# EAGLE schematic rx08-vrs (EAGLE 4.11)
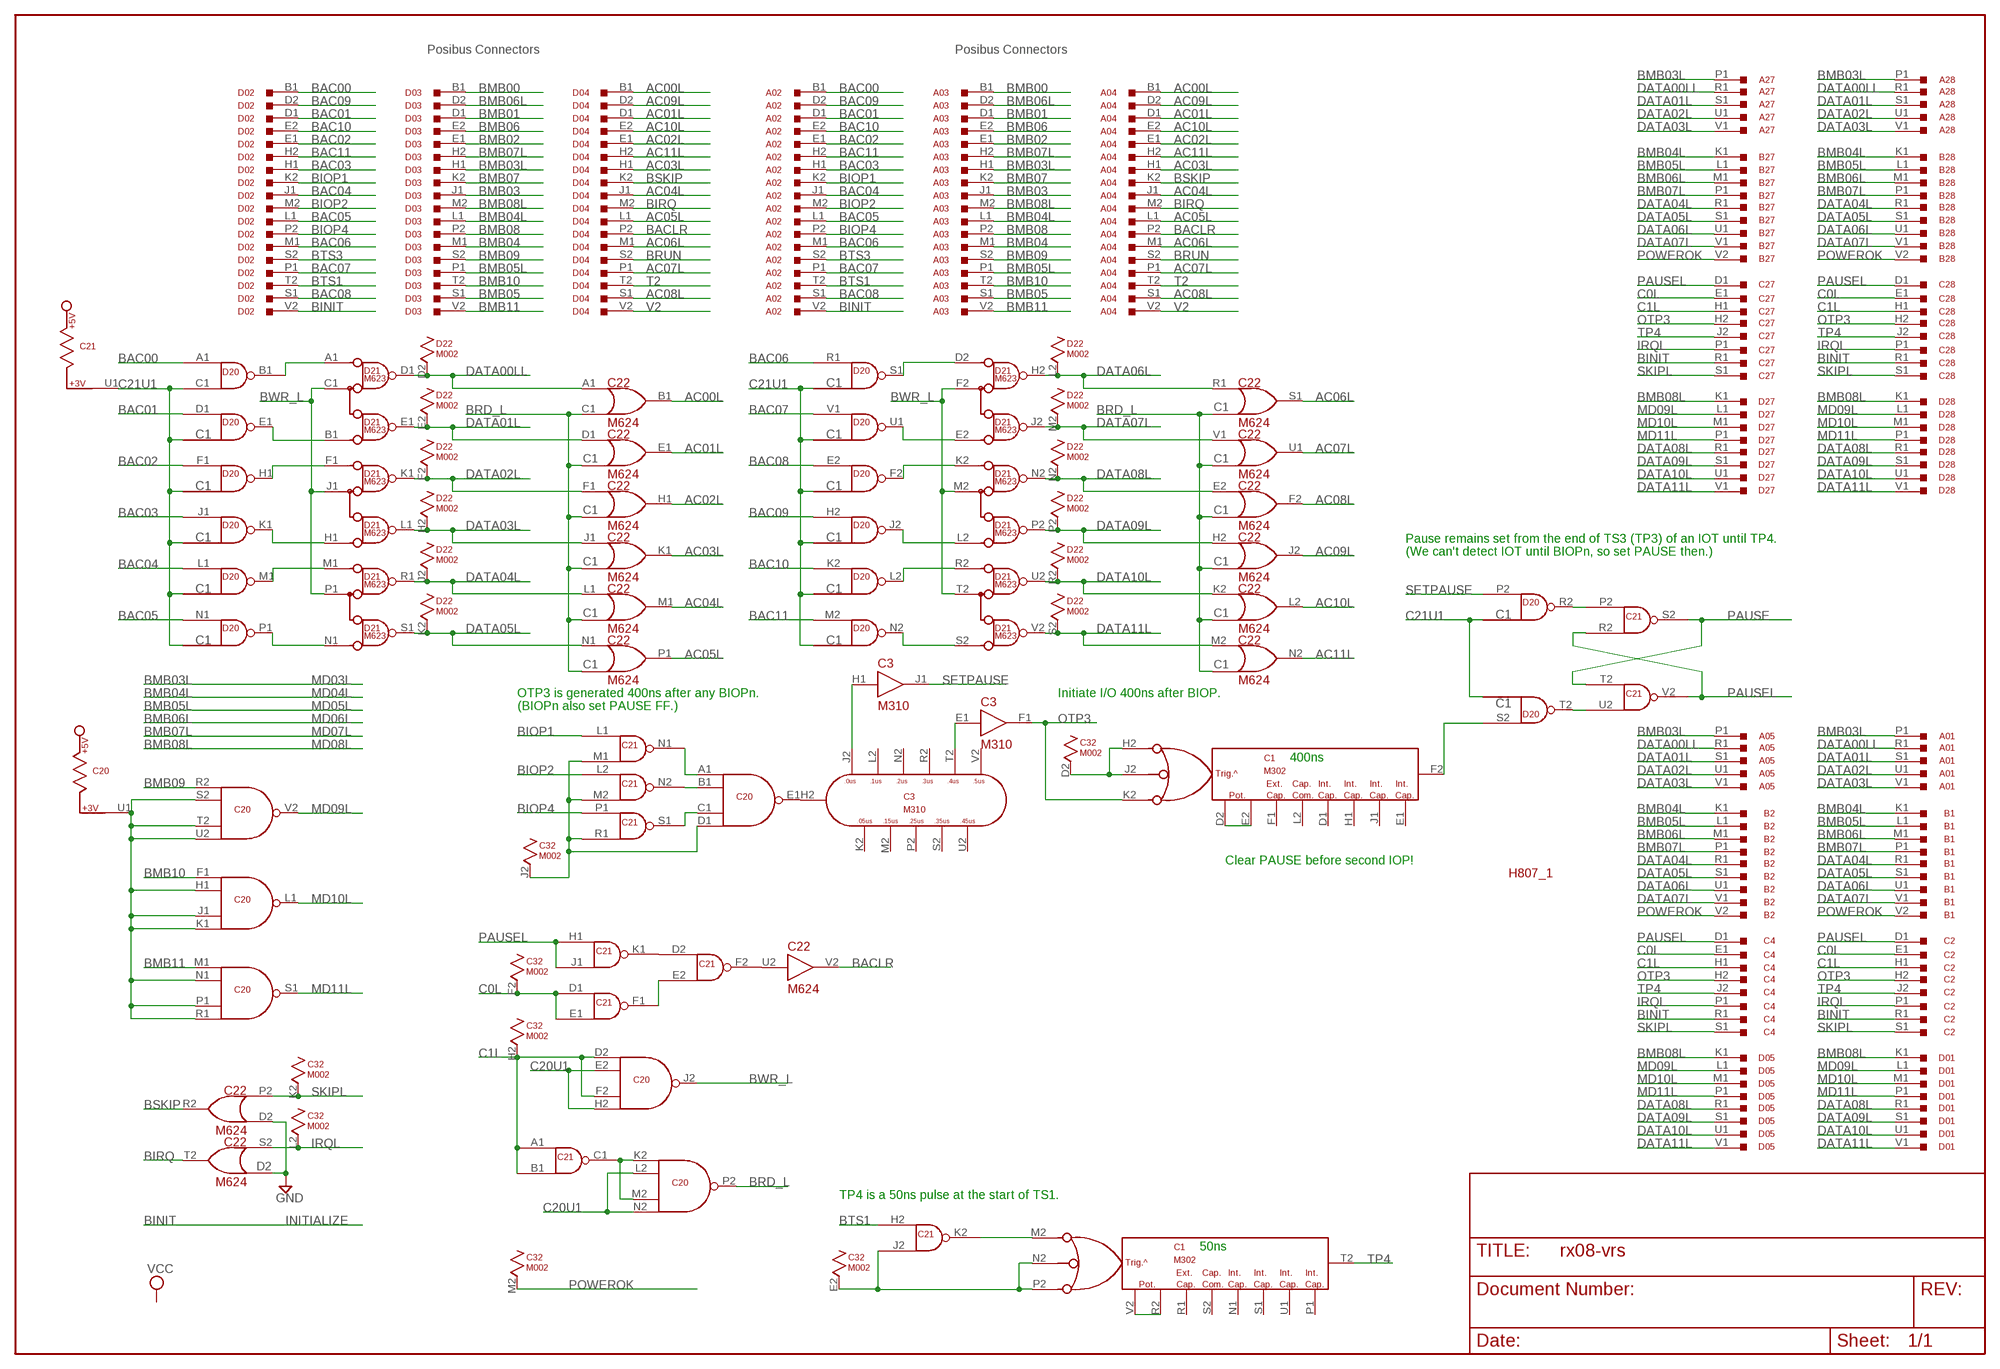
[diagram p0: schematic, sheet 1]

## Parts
A01  M916  [H807]
A02  M903  [H807]
A03  M903  [H807]
A04  M903  [H807]
A05  M916  [H807]
A27  M916  [H807]
A28  M916  [H807]
B1  M916  [H807]
B2  M916  [H807]
B27  M916  [H807]
B28  M916  [H807]
C1  M302  [H807]
C2  M916  [H807]
C3  M310  [H807]
C4  M916  [H807]
C20  M617  [H807]
C21  M113  [H807]
C22  M624  [H807]
C27  M916  [H807]
C28  M916  [H807]
C32  M002  [H807]
D01  M916  [H807]
D02  M903  [H807]
D03  M903  [H807]
D04  M903  [H807]
D05  M916  [H807]
D20  M101  [H807]
D21  M623  [H807]
D22  M002  [H807]
D27  M916  [H807]
D28  M916  [H807]
H807_1  H807  [H807]

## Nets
AC00L: A04.B1 C22.B1(OUT) D04.B1
AC01L: A04.D1 C22.E1(OUT) D04.D1
AC02L: A04.E1 C22.H1(OUT) D04.E1
AC03L: A04.H1 C22.K1(OUT) D04.H1
AC04L: A04.J1 C22.M1(OUT) D04.J1
AC05L: A04.L1 C22.P1(OUT) D04.L1
AC06L: A04.M1 C22.S1(OUT) D04.M1
AC07L: A04.P1 C22.U1(OUT) D04.P1
AC08L: A04.S1 C22.F2(OUT) D04.S1
AC09L: A04.D2 C22.J2(OUT) D04.D2
AC10L: A04.E2 C22.L2(OUT) D04.E2
AC11L: A04.H2 C22.N2(OUT) D04.H2
BAC00: A02.B1 D02.B1 D20.A1(IN1)
BAC01: A02.D1 D02.D1 D20.D1(IN)
BAC02: A02.E1 D02.E1 D20.F1(IN)
BAC03: A02.H1 D02.H1 D20.J1(IN)
BAC04: A02.J1 D02.J1 D20.L1(IN)
BAC05: A02.L1 D02.L1 D20.N1(IN)
BAC06: A02.M1 D02.M1 D20.R1(IN)
BAC07: A02.P1 D02.P1 D20.V1(IN)
BAC08: A02.S1 D02.S1 D20.E2(IN)
BAC09: A02.D2 D02.D2 D20.H2(IN)
BAC10: A02.E2 D02.E2 D20.K2(IN)
BAC11: A02.H2 D02.H2 D20.M2(IN)
BACLR: A04.P2 C22.V2(OUT) D04.P2
BINIT: A02.V2 C2.R1 C4.R1 C27.R1 C28.R1 D02.V2
BIOP1: A02.K2 C21.L1(IN1) D02.K2
BIOP2: A02.M2 C21.L2(IN1) D02.M2
BIOP4: A02.P2 C21.P1(IN1) D02.P2
BIRQ: A04.M2 C22.T2(OUT) D04.M2
BMB00: A03.B1 D03.B1
BMB01: A03.D1 D03.D1
BMB02: A03.E1 D03.E1
BMB03: A03.J1 D03.J1
BMB03L: A01.P1 A03.H1 A05.P1 A27.P1 A28.P1 D03.H1
BMB04: A03.M1 D03.M1
BMB04L: A03.L1 B1.K1 B2.K1 B27.K1 B28.K1 D03.L1
BMB05: A03.S1 D03.S1
BMB05L: A03.P1 B1.L1 B2.L1 B27.L1 B28.L1 D03.P1
BMB06: A03.E2 D03.E2
BMB06L: A03.D2 B1.M1 B2.M1 B27.M1 B28.M1 D03.D2
BMB07: A03.K2 D03.K2
BMB07L: A03.H2 B1.P1 B2.P1 B27.P1 B28.P1 D03.H2
BMB08: A03.P2 D03.P2
BMB08L: A03.M2 D01.K1 D03.M2 D05.K1 D27.K1 D28.K1
BMB09: A03.S2 C20.R2(IN1) D03.S2
BMB10: A03.T2 C20.F1(IN1) D03.T2
BMB11: A03.V2 C20.M1(IN1) D03.V2
BRD_L: C20.P2(OUT) C22.C1(IN2)
BRUN: A04.S2 D04.S2
BSKIP: A04.K2 C22.R2(OUT) D04.K2
BTS1: A02.T2 C21.H2(IN1) D02.T2
BTS3: A02.S2 D02.S2
BWR_L: C20.J2(OUT) D21.C1(C) D21.F2(C) D21.J1(C) D21.M2(C) D21.P1(C) D21.T2(C)
C0L: C2.E1 C4.E1 C21.D1(IN1) C21.E1(IN2) C27.E1 C28.E1 C32.F2
C1L: C2.H1 C4.H1 C20.D2(IN1) C20.F2(IN3) C21.A1(IN1) C21.B1(IN2) C27.H1 C28.H1 C32.H2
C20U1: C20.E2(IN2) C20.H1(IN2) C20.H2(IN4) C20.J1(IN3) C20.K1(IN4) C20.L2(IN2) C20.N1(IN2) C20.N2(IN4) C20.P1(IN3) C20.R1(IN4) C20.S2(IN2) C20.T2(IN3) C20.U1 C20.U2(IN4)
C21U1: C21.U1 D20.C1(IN2)
DATA00LL: A01.R1 A05.R1 A27.R1 A28.R1 C22.A1(IN1) D21.D1(D) D22.D2
DATA01L: A01.S1 A05.S1 A27.S1 A28.S1 C22.D1(IN) D21.E1(E) D22.E2
DATA02L: A01.U1 A05.U1 A27.U1 A28.U1 C22.F1(IN) D21.K1(D) D22.F2
DATA03L: A01.V1 A05.V1 A27.V1 A28.V1 C22.J1(IN) D21.L1(E) D22.H2
DATA04L: B1.R1 B2.R1 B27.R1 B28.R1 C22.L1(IN) D21.R1(D) D22.J2
DATA05L: B1.S1 B2.S1 B27.S1 B28.S1 C22.N1(IN) D21.S1(E) D22.K2
DATA06L: B1.U1 B2.U1 B27.U1 B28.U1 C22.R1(IN) D21.H2(D) D22.L2
DATA07L: B1.V1 B2.V1 B27.V1 B28.V1 C22.V1(IN) D21.J2(E) D22.M2
DATA08L: C22.E2(IN) D01.R1 D05.R1 D21.N2(D) D22.N2 D27.R1 D28.R1
DATA09L: C22.H2(IN) D01.S1 D05.S1 D21.P2(E) D22.P2 D27.S1 D28.S1
DATA10L: C22.K2(IN) D01.U1 D05.U1 D21.U2(D) D22.R2 D27.U1 D28.U1
DATA11L: C22.M2(IN) D01.V1 D05.V1 D21.V2(E) D22.S2 D27.V1 D28.V1
GND: C22.D2(IN2)
IRQL: C2.P1 C4.P1 C22.S2(IN) C27.P1 C28.P1 C32.L2
MD09L: C20.V2(OUT) D01.L1 D05.L1 D27.L1 D28.L1
MD10L: C20.L1(OUT) D01.M1 D05.M1 D27.M1 D28.M1
MD11L: C20.S1(OUT) D01.P1 D05.P1 D27.P1 D28.P1
N$1: D20.B1(OUT) D21.A1(A)
N$2: D20.E1(OUT) D21.B1(B)
N$3: D20.H1(OUT) D21.F1(A)
N$4: D20.K1(OUT) D21.H1(B)
N$5: D20.P1(OUT) D21.N1(B)
N$6: D20.M1(OUT) D21.M1(A)
N$7: C20.K2(IN1) C20.M2(IN3) C21.C1(OUT)
N$8: D20.N2(OUT) D21.S2(B)
N$9: C1.F2 D20.S2(IN)
N$10: D20.J2(OUT) D21.L2(B)
N$11: D20.U1(OUT) D21.E2(B)
N$12: D20.S1(OUT) D21.D2(A)
N$13: D20.F2(OUT) D21.K2(A)
N$14: D20.L2(OUT) D21.R2(A)
N$15: C21.P2(IN1) D20.R2(OUT)
N$16: C1.H2 C1.J2 C32.D2
N$17: C21.U2(IN2) D20.T2(OUT)
N$19: C21.E2(IN2) C21.F1(OUT)
N$20: C21.D2(IN1) C21.K1(OUT)
N$23: C21.F2(OUT) C22.U2(IN)
N$27: C3.H2 C20.E1(OUT)
N$31: C3.E1(IN) C3.T2
N$32: C20.C1(IN3) C21.S1(OUT)
N$33: C20.A1(IN1) C21.N1(OUT)
N$34: C20.B1(IN2) C21.N2(OUT)
N$35: C1.D2 C1.E2
N$36: C1.M2(H2) C21.K2(OUT)
N$37: C1.R2(E2) C1.V2(D2)
N$38: C3.H1(IN) C3.J2
N$40: C1.N2(J2) C1.P2(K2) C21.J2(IN2) C32.E2
N$43: C20.D1(IN4) C21.M1(IN2) C21.M2(IN2) C21.R1(IN2) C32.J2
OTP3: C1.K2 C2.H2 C3.F1(OUT) C4.H2 C27.H2 C28.H2
PAUSE: C21.S2(OUT) C21.T2(IN1)
PAUSEL: C2.D1 C4.D1 C21.H1(IN1) C21.J1(IN2) C21.R2(IN2) C21.V2(OUT) C27.D1 C28.D1
POWEROK: B1.V2 B2.V2 B27.V2 B28.V2 C32.M2
SETPAUSE: C3.J1(OUT) D20.P2(IN)
SKIPL: C2.S1 C4.S1 C22.P2(IN1) C27.S1 C28.S1 C32.K2
T2: A04.T2 D04.T2
TP4: C1.T2(F2) C2.J2 C4.J2 C27.J2 C28.J2
V2: A04.V2 D04.V2
Unconnected: A01.A1 A01.A2 A01.B1 A01.B2 A01.C1 A01.C2 A01.D1 A01.D2 A01.E1 A01.E2 A01.F1 A01.F2 A01.H1 A01.H2 A01.J1 A01.J2 A01.K1 A01.K2 A01.L1 A01.L2 A01.M1 A01.M2 A01.N1 A01.N2 A01.P2 A01.R2 A01.S2 A01.T1 A01.T2 A01.U2 A01.V2 A05.A1 A05.A2 A05.B1 A05.B2 A05.C1 A05.C2 A05.D1 A05.D2 A05.E1 A05.E2 A05.F1 A05.F2 A05.H1 A05.H2 A05.J1 A05.J2 A05.K1 A05.K2 A05.L1 A05.L2 A05.M1 A05.M2 A05.N1 A05.N2 A05.P2 A05.R2 A05.S2 A05.T1 A05.T2 A05.U2 A05.V2 A27.A1 A27.A2 A27.B1 A27.B2 A27.C1 A27.C2 A27.D1 A27.D2 A27.E1 A27.E2 A27.F1 A27.F2 A27.H1 A27.H2 A27.J1 A27.J2 A27.K1 A27.K2 A27.L1 A27.L2 A27.M1 A27.M2 A27.N1 A27.N2 A27.P2 A27.R2 A27.S2 A27.T1 A27.T2 A27.U2 A27.V2 A28.A1 A28.A2 A28.B1 A28.B2 A28.C1 A28.C2 A28.D1 A28.D2 A28.E1 A28.E2 A28.F1 A28.F2 A28.H1 A28.H2 A28.J1 A28.J2 A28.K1 A28.K2 A28.L1 A28.L2 A28.M1 A28.M2 A28.N1 A28.N2 A28.P2 A28.R2 A28.S2 A28.T1 A28.T2 A28.U2 A28.V2 B1.A1 B1.A2 B1.B1 B1.B2 B1.C1 B1.C2 B1.D1 B1.D2 B1.E1 B1.E2 B1.F1 B1.F2 B1.H1 B1.H2 B1.J1 B1.J2 B1.K2 B1.L2 B1.M2 B1.N1 B1.N2 B1.P2 B1.R2 B1.S2 B1.T1 B1.T2 B1.U2 B2.A1 B2.A2 B2.B1 B2.B2 B2.C1 B2.C2 B2.D1 B2.D2 B2.E1 B2.E2 B2.F1 B2.F2 B2.H1 B2.H2 B2.J1 B2.J2 B2.K2 B2.L2 B2.M2 B2.N1 B2.N2 B2.P2 B2.R2 B2.S2 B2.T1 B2.T2 B2.U2 B27.A1 B27.A2 B27.B1 B27.B2 B27.C1 B27.C2 B27.D1 B27.D2 B27.E1 B27.E2 B27.F1 B27.F2 B27.H1 B27.H2 B27.J1 B27.J2 B27.K2 B27.L2 B27.M2 B27.N1 B27.N2 B27.P2 B27.R2 B27.S2 B27.T1 B27.T2 B27.U2 B28.A1 B28.A2 B28.B1 B28.B2 B28.C1 B28.C2 B28.D1 B28.D2 B28.E1 B28.E2 B28.F1 B28.F2 B28.H1 B28.H2 B28.J1 B28.J2 B28.K2 B28.L2 B28.M2 B28.N1 B28.N2 B28.P2 B28.R2 B28.S2 B28.T1 B28.T2 B28.U2 C1.D1 C1.E1 C1.F1 C1.H1 C1.J1 C1.L2 C1.N1(D1) C1.P1(E1) C1.R1(F1) C1.S1(H1) C1.S2(L2) C1.U1(J1) C2.A1 C2.A2 C2.B1 C2.B2 C2.C1 C2.C2 C2.D2 C2.E2 C2.F1 C2.F2 C2.J1 C2.K1 C2.K2 C2.L1 C2.L2 C2.M1 C2.M2 C2.N1 C2.N2 C2.P2 C2.R2 C2.S2 C2.T1 C2.T2 C2.U1 C2.U2 C2.V1 C2.V2 C3.K2 C3.L2 C3.M2 C3.N2 C3.P2 C3.R2 C3.S2 C3.U2 C3.V2 C4.A1 C4.A2 C4.B1 C4.B2 C4.C1 C4.C2 C4.D2 C4.E2 C4.F1 C4.F2 C4.J1 C4.K1 C4.K2 C4.L1 C4.L2 C4.M1 C4.M2 C4.N1 C4.N2 C4.P2 C4.R2 C4.S2 C4.T1 C4.T2 C4.U1 C4.U2 C4.V1 C4.V2 C20.V1 C21.V1 C27.A1 C27.A2 C27.B1 C27.B2 C27.C1 C27.C2 C27.D2 C27.E2 C27.F1 C27.F2 C27.J1 C27.K1 C27.K2 C27.L1 C27.L2 C27.M1 C27.M2 C27.N1 C27.N2 C27.P2 C27.R2 C27.S2 C27.T1 C27.T2 C27.U1 C27.U2 C27.V1 C27.V2 C28.A1 C28.A2 C28.B1 C28.B2 C28.C1 C28.C2 C28.D2 C28.E2 C28.F1 C28.F2 C28.J1 C28.K1 C28.K2 C28.L1 C28.L2 C28.M1 C28.M2 C28.N1 C28.N2 C28.P2 C28.R2 C28.S2 C28.T1 C28.T2 C28.U1 C28.U2 C28.V1 C28.V2 C32.N2 C32.P2 C32.R2 C32.S2 C32.T2 C32.U2 C32.V2 D01.A1 D01.A2 D01.B1 D01.B2 D01.C1 D01.C2 D01.D1 D01.D2 D01.E1 D01.E2 D01.F1 D01.F2 D01.H1 D01.H2 D01.J1 D01.J2 D01.K2 D01.L2 D01.M2 D01.N1 D01.N2 D01.P2 D01.R2 D01.S2 D01.T1 D01.T2 D01.U2 D01.V2 D05.A1 D05.A2 D05.B1 D05.B2 D05.C1 D05.C2 D05.D1 D05.D2 D05.E1 D05.E2 D05.F1 D05.F2 D05.H1 D05.H2 D05.J1 D05.J2 D05.K2 D05.L2 D05.M2 D05.N1 D05.N2 D05.P2 D05.R2 D05.S2 D05.T1 D05.T2 D05.U2 D05.V2 D20.U2(IN) D20.V2(OUT) D22.T2 D22.U2 D22.V2 D27.A1 D27.A2 D27.B1 D27.B2 D27.C1 D27.C2 D27.D1 D27.D2 D27.E1 D27.E2 D27.F1 D27.F2 D27.H1 D27.H2 D27.J1 D27.J2 D27.K2 D27.L2 D27.M2 D27.N1 D27.N2 D27.P2 D27.R2 D27.S2 D27.T1 D27.T2 D27.U2 D27.V2 D28.A1 D28.A2 D28.B1 D28.B2 D28.C1 D28.C2 D28.D1 D28.D2 D28.E1 D28.E2 D28.F1 D28.F2 D28.H1 D28.H2 D28.J1 D28.J2 D28.K2 D28.L2 D28.M2 D28.N1 D28.N2 D28.P2 D28.R2 D28.S2 D28.T1 D28.T2 D28.U2 D28.V2

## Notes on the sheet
- Posibus Connectors | Posibus Connectors
- Pause remains set from the end of TS3 (TP3) of an IOT until TP4.
- (We can't detect IOT until BIOPn, so set PAUSE then.)
- MD03L
- MD04L | OTP3 is generated 400ns after any BIOPn. | Initiate I/O 400ns after BIOP.
- MD05L | (BIOPn also set PAUSE FF.)
- MD06L
- MD07L
- MD08L
- 400ns
- Clear PAUSE before second IOP!
- TP4 is a 50ns pulse at the start of TS1.
- INITIALIZE
- 50ns

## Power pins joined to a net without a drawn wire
GND: A02.A1 A02.C1 A02.C2 A02.F1 A02.F2 A02.J2 A02.K1 A02.L2 A02.N1 A02.N2 A02.R1 A02.R2 A02.T1 A02.U2 A03.A1 A03.C1 A03.C2 A03.F1 A03.F2 A03.J2 A03.K1 A03.L2 A03.N1 A03.N2 A03.R1 A03.R2 A03.T1 A03.U2 A04.A1 A04.C1 A04.C2 A04.F1 A04.F2 A04.J2 A04.K1 A04.L2 A04.N1 A04.N2 A04.R1 A04.R2 A04.T1 A04.U2 C1.C2(GND) C1.T1(GND) C3.C2(GND) C3.T1(GND) C20.C2(GND) C20.T1(GND) C21.C2(GND) C21.T1(GND) C22.C2(GND) C22.T1(GND) C32.C2(GND) D02.A1 D02.C1 D02.C2 D02.F1 D02.F2 D02.J2 D02.K1 D02.L2 D02.N1 D02.N2 D02.R1 D02.R2 D02.T1 D02.U2 D03.A1 D03.C1 D03.C2 D03.F1 D03.F2 D03.J2 D03.K1 D03.L2 D03.N1 D03.N2 D03.R1 D03.R2 D03.T1 D03.U2 D04.A1 D04.C1 D04.C2 D04.F1 D04.F2 D04.J2 D04.K1 D04.L2 D04.N1 D04.N2 D04.R1 D04.R2 D04.T1 D04.U2 D20.C2(GND) D20.T1(GND) D21.C2(GND) D21.T1(GND) D21.U1(GND) D21.V1(GND) D22.C2(GND)
VCC: C1.A2(VCC) C3.A2(VCC) C20.A2(VCC) C21.A2(VCC) C22.A2(VCC) C32.A2(VCC) D20.A2(VCC) D21.A2(VCC) D22.A2(VCC)

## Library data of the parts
A01 A05 A27 A28 B1 B2 B27 B28 C2 C4 C27 C28 D01 D05 D27 D28 = dec-m:M916: Simple 36 pin connector/wire cable
A02-A04 D02-D04 = dec-m:M903: Two-sided Posibus cable/connector.
C1 = dec-m:M302: Dual one-shot
C3 = dec-m:M310: Tapped Delay Line
C20 = dec-m:M617: 6 4-input NAND Buffers
C21 = dec-m:M113: 10 2-input NAND Gates
C22 = dec-m:M624: Bus Data Interface The M101 contains 15 two-input NAND gates. One input of each gate is tied to a common line so that all data signals can be enabled simultaneously. Each data signal presents one TTL load. The common input presents 15 loads. Each output can drive 10 loads. Power: 5V@82ma (max.)
C32 D22 = dec-m:M002: 15 Clamped Loads
D20 = dec-m:M101: Bus Data Interface The M101 contains 15 two-input NAND gates. One input of each gate is tied to a common line so that all data signals can be enabled simultaneously. Each data signal presents one TTL load. The common input presents 15 loads. Each output can drive 10 loads. Power: 5V@82ma (max.)
D21 = dec-m:M623: 6 Dual Bus Drivers
H807_1 = dec-m:H807: Empty card slot

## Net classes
1 Supply: width 1.905 mm, drill 0.508 mm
